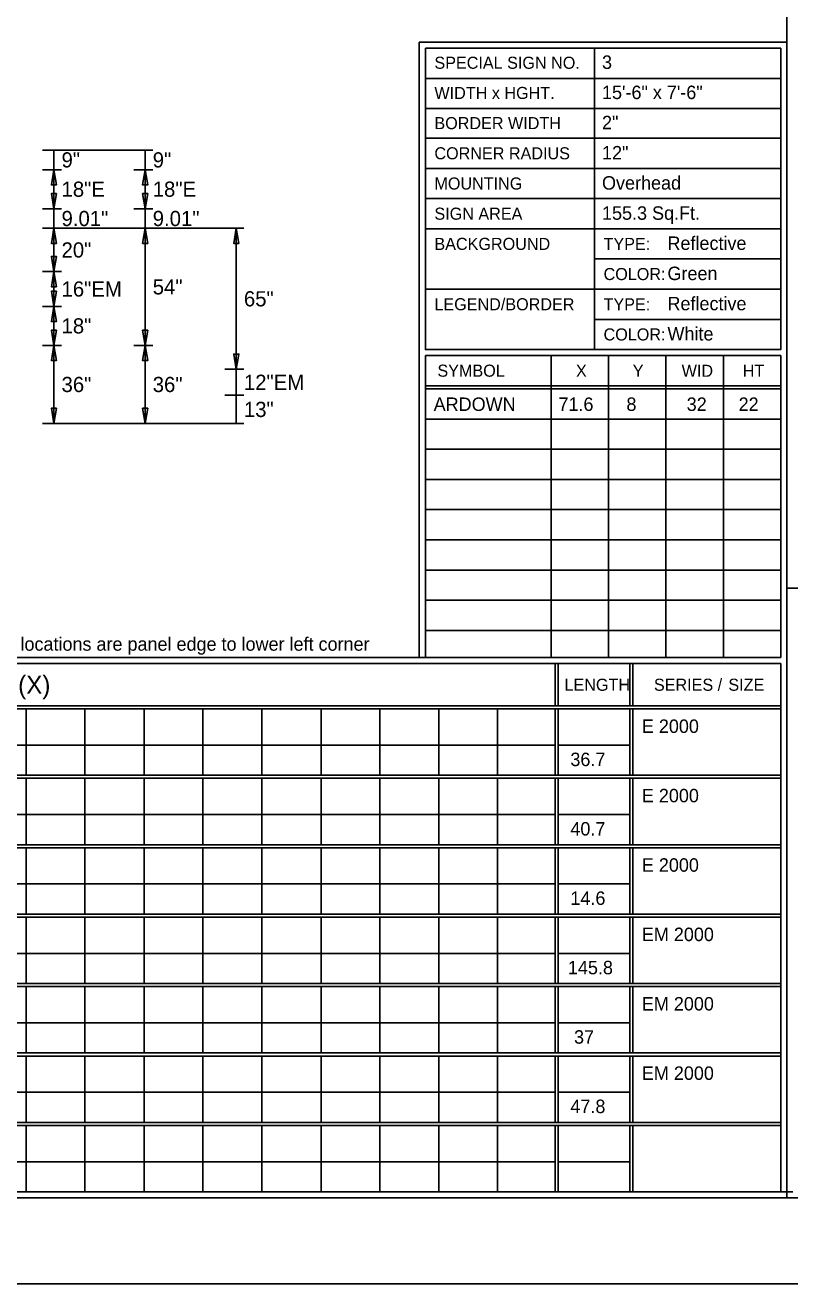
# Model space of a CAD drawing. Extents: x 2149961 to 2150220, y 145114 to 145240.
# Drawn here: x 2150047.08 to 2150076.43, y 145114.09 to 145162.43 of the extents above; entities that cross this region are included whole.
import ezdxf

# ---------------------------------------------------------------- set-up
doc = ezdxf.new("R2010")
doc.units = 0
for name, color, linetype in [('BORDER', 7, 'Continuous'), ('GSDIMS', 7, 'Continuous'), ('GSSHT', 7, 'Continuous'), ('Level 1', 7, 'Continuous'), ('PDF', 7, 'Continuous')]:
    doc.layers.add(name, color=color, linetype=linetype)

msp = doc.modelspace()

# ---------------------------------------------------------------- linework, layer by layer
at = {"layer": 'BORDER'}
for p, q in [((2150017.557, 145117.388), (2150171.536, 145117.388)), ((2150010.458, 145114.088), (2150174.061, 145114.088))]:
    msp.add_line(p, q, dxfattribs=at)
at = {"layer": 'GSDIMS'}
for p, q in [((2150047.749, 145157.634), (2150048.478, 145157.634)), ((2150047.749, 145157.634), (2150051.249, 145157.634)), ((2150048.187, 145156.883), (2150048.187, 145157.634)), ((2150051.249, 145157.634), (2150051.978, 145157.634)), ((2150051.687, 145156.883), (2150051.687, 145157.634)), ((2150047.749, 145156.883), (2150048.478, 145156.883)), ((2150047.749, 145156.883), (2150048.478, 145156.883)), ((2150048.187, 145156.883), (2150048.187, 145155.383)), ((2150051.249, 145156.883), (2150051.978, 145156.883)), ((2150051.249, 145156.883), (2150051.978, 145156.883)), ((2150051.687, 145156.883), (2150051.687, 145155.383)), ((2150047.749, 145155.383), (2150048.478, 145155.383)), ((2150047.749, 145155.383), (2150048.478, 145155.383)), ((2150048.187, 145154.633), (2150048.187, 145155.383)), ((2150051.249, 145155.383), (2150051.978, 145155.383)), ((2150051.249, 145155.383), (2150051.978, 145155.383)), ((2150051.687, 145154.633), (2150051.687, 145155.383)), ((2150047.749, 145154.633), (2150048.478, 145154.633)), ((2150047.749, 145154.633), (2150054.749, 145154.633)), ((2150047.749, 145154.633), (2150048.478, 145154.633)), ((2150047.749, 145154.633), (2150051.249, 145154.633)), ((2150048.187, 145152.966), (2150048.187, 145154.633)), ((2150051.249, 145154.633), (2150051.978, 145154.633)), ((2150051.249, 145154.633), (2150051.978, 145154.633)), ((2150051.687, 145150.133), (2150051.687, 145154.633)), ((2150054.749, 145154.633), (2150055.478, 145154.633)), ((2150055.187, 145149.216), (2150055.187, 145154.633)), ((2150047.749, 145152.966), (2150048.478, 145152.966)), ((2150047.749, 145152.966), (2150048.478, 145152.966)), ((2150048.187, 145152.966), (2150048.187, 145151.633)), ((2150047.749, 145151.633), (2150048.478, 145151.633)), ((2150047.749, 145151.633), (2150048.478, 145151.633)), ((2150048.187, 145150.133), (2150048.187, 145151.633)), ((2150047.749, 145150.133), (2150048.478, 145150.133)), ((2150047.749, 145150.133), (2150048.478, 145150.133)), ((2150048.187, 145150.133), (2150048.187, 145147.133)), ((2150051.249, 145150.133), (2150051.978, 145150.133)), ((2150051.249, 145150.133), (2150051.978, 145150.133)), ((2150051.687, 145150.133), (2150051.687, 145147.133)), ((2150054.749, 145149.216), (2150055.478, 145149.216)), ((2150054.749, 145149.216), (2150055.478, 145149.216)), ((2150055.187, 145149.216), (2150055.187, 145148.216)), ((2150054.749, 145148.216), (2150055.478, 145148.216)), ((2150054.749, 145148.216), (2150055.478, 145148.216)), ((2150055.187, 145147.133), (2150055.187, 145148.216)), ((2150047.749, 145147.133), (2150048.478, 145147.133)), ((2150047.749, 145147.133), (2150054.749, 145147.133)), ((2150051.249, 145147.133), (2150051.978, 145147.133)), ((2150054.749, 145147.133), (2150055.478, 145147.133))]:
    msp.add_line(p, q, dxfattribs=at)
for points in [[(2150048.187, 145156.883), (2150048.09, 145156.3), (2150048.284, 145156.3)], [(2150051.687, 145156.883), (2150051.59, 145156.3), (2150051.784, 145156.3)], [(2150048.187, 145155.383), (2150048.09, 145155.967), (2150048.284, 145155.967)], [(2150051.687, 145155.383), (2150051.59, 145155.967), (2150051.784, 145155.967)], [(2150048.187, 145154.633), (2150048.09, 145154.05), (2150048.284, 145154.05)], [(2150051.687, 145154.633), (2150051.59, 145154.05), (2150051.784, 145154.05)], [(2150055.187, 145154.633), (2150055.09, 145154.05), (2150055.284, 145154.05)], [(2150048.187, 145152.966), (2150048.09, 145153.55), (2150048.284, 145153.55)], [(2150048.187, 145152.966), (2150048.09, 145152.383), (2150048.284, 145152.383)], [(2150048.187, 145151.633), (2150048.09, 145152.216), (2150048.284, 145152.216)], [(2150048.187, 145151.633), (2150048.09, 145151.05), (2150048.284, 145151.05)], [(2150048.187, 145150.133), (2150048.09, 145150.717), (2150048.284, 145150.717)], [(2150051.687, 145150.133), (2150051.59, 145150.717), (2150051.784, 145150.717)], [(2150048.187, 145150.133), (2150048.09, 145149.55), (2150048.284, 145149.55)], [(2150051.687, 145150.133), (2150051.59, 145149.55), (2150051.784, 145149.55)], [(2150055.187, 145149.216), (2150055.09, 145149.8), (2150055.284, 145149.8)], [(2150048.187, 145147.133), (2150048.09, 145147.716), (2150048.284, 145147.716)], [(2150051.687, 145147.133), (2150051.59, 145147.716), (2150051.784, 145147.716)]]:
    msp.add_lwpolyline(points, close=True, dxfattribs=at)
at = {"layer": 'Level 1'}
for p, q in [((2150076.316, 145216.512), (2150076.316, 145117.388)), ((2150062.21, 145161.778), (2150076.316, 145161.778)), ((2150068.935, 145161.546), (2150068.935, 145149.975)), ((2150062.442, 145160.387), (2150076.084, 145160.387)), ((2150062.442, 145159.227), (2150076.084, 145159.227)), ((2150062.442, 145158.091), (2150076.084, 145158.091)), ((2150062.442, 145156.932), (2150076.084, 145156.932)), ((2150062.442, 145155.772), (2150076.084, 145155.772)), ((2150062.442, 145154.613), (2150076.084, 145154.613)), ((2150068.935, 145153.453), (2150076.084, 145153.453)), ((2150062.442, 145152.294), (2150076.084, 145152.294)), ((2150068.935, 145151.134), (2150076.084, 145151.134)), ((2150062.442, 145138.143), (2150062.442, 145149.743)), ((2150062.442, 145149.743), (2150076.084, 145149.743)), ((2150067.272, 145149.737), (2150067.272, 145148.578)), ((2150069.475, 145149.737), (2150069.475, 145148.578)), ((2150071.678, 145149.737), (2150071.678, 145148.578)), ((2150073.881, 145149.737), (2150073.881, 145148.578)), ((2150076.084, 145149.743), (2150076.084, 145138.143)), ((2150062.442, 145148.578), (2150076.084, 145148.578)), ((2150062.442, 145148.462), (2150076.084, 145148.462)), ((2150067.272, 145148.578), (2150067.272, 145138.143)), ((2150069.475, 145148.578), (2150069.475, 145138.143)), ((2150071.678, 145148.578), (2150071.678, 145138.143)), ((2150073.881, 145148.578), (2150073.881, 145138.143)), ((2150062.442, 145147.303), (2150076.084, 145147.303)), ((2150062.442, 145146.143), (2150076.084, 145146.143)), ((2150062.442, 145144.984), (2150076.084, 145144.984)), ((2150062.442, 145143.824), (2150076.084, 145143.824)), ((2150062.442, 145142.665), (2150076.084, 145142.665)), ((2150062.442, 145141.505), (2150076.084, 145141.505)), ((2150076.316, 145140.809), (2150121.342, 145140.809)), ((2150062.442, 145140.346), (2150076.084, 145140.346)), ((2150062.442, 145139.186), (2150076.084, 145139.186)), ((2150017.557, 145138.143), (2150062.583, 145138.143)), ((2150076.084, 145138.143), (2150062.442, 145138.143)), ((2150067.426, 145137.911), (2150067.426, 145136.288)), ((2150067.542, 145137.911), (2150067.542, 145136.288)), ((2150070.29, 145137.911), (2150070.29, 145136.288)), ((2150070.405, 145137.911), (2150070.405, 145136.288)), ((2150017.789, 145136.288), (2150076.084, 145136.288)), ((2150017.789, 145136.172), (2150076.084, 145136.172)), ((2150047.124, 145136.172), (2150047.124, 145133.621)), ((2150049.373, 145136.172), (2150049.373, 145133.621)), ((2150051.646, 145136.172), (2150051.646, 145133.621)), ((2150053.895, 145136.172), (2150053.895, 145133.621)), ((2150056.168, 145136.172), (2150056.168, 145133.621)), ((2150058.441, 145136.172), (2150058.441, 145133.621)), ((2150060.69, 145136.172), (2150060.69, 145133.621)), ((2150062.962, 145136.172), (2150062.962, 145133.621)), ((2150065.212, 145136.172), (2150065.212, 145133.621)), ((2150067.426, 145136.172), (2150067.426, 145133.621)), ((2150067.542, 145136.172), (2150067.542, 145133.621)), ((2150070.29, 145136.172), (2150070.29, 145133.621)), ((2150070.405, 145136.172), (2150070.405, 145133.621)), ((2150017.789, 145134.78), (2150067.426, 145134.78)), ((2150067.542, 145134.78), (2150070.29, 145134.78)), ((2150017.789, 145133.621), (2150076.084, 145133.621)), ((2150017.789, 145133.505), (2150076.084, 145133.505)), ((2150047.124, 145133.505), (2150047.124, 145130.954)), ((2150049.373, 145133.505), (2150049.373, 145130.954)), ((2150051.646, 145133.505), (2150051.646, 145130.954)), ((2150053.895, 145133.505), (2150053.895, 145130.954)), ((2150056.168, 145133.505), (2150056.168, 145130.954)), ((2150058.441, 145133.505), (2150058.441, 145130.954)), ((2150060.69, 145133.505), (2150060.69, 145130.954)), ((2150062.962, 145133.505), (2150062.962, 145130.954)), ((2150065.212, 145133.505), (2150065.212, 145130.954)), ((2150067.426, 145133.505), (2150067.426, 145130.954)), ((2150067.542, 145133.505), (2150067.542, 145130.954)), ((2150070.29, 145133.505), (2150070.29, 145130.954)), ((2150070.405, 145133.505), (2150070.405, 145130.954)), ((2150017.789, 145132.113), (2150067.426, 145132.113)), ((2150067.542, 145132.113), (2150070.29, 145132.113)), ((2150017.789, 145130.954), (2150076.084, 145130.954)), ((2150017.789, 145130.838), (2150076.084, 145130.838)), ((2150047.124, 145130.838), (2150047.124, 145128.287)), ((2150049.373, 145130.838), (2150049.373, 145128.287)), ((2150051.646, 145130.838), (2150051.646, 145128.287)), ((2150053.895, 145130.838), (2150053.895, 145128.287)), ((2150056.168, 145130.838), (2150056.168, 145128.287)), ((2150058.441, 145130.838), (2150058.441, 145128.287)), ((2150060.69, 145130.838), (2150060.69, 145128.287)), ((2150062.962, 145130.838), (2150062.962, 145128.287)), ((2150065.212, 145130.838), (2150065.212, 145128.287)), ((2150067.426, 145130.838), (2150067.426, 145128.287)), ((2150067.542, 145130.838), (2150067.542, 145128.287)), ((2150070.29, 145130.838), (2150070.29, 145128.287)), ((2150070.405, 145130.838), (2150070.405, 145128.287)), ((2150017.789, 145129.447), (2150067.426, 145129.447)), ((2150067.542, 145129.447), (2150070.29, 145129.447)), ((2150017.789, 145128.287), (2150076.084, 145128.287)), ((2150017.789, 145128.171), (2150076.084, 145128.171)), ((2150047.124, 145128.171), (2150047.124, 145125.62)), ((2150049.373, 145128.171), (2150049.373, 145125.62)), ((2150051.646, 145128.171), (2150051.646, 145125.62)), ((2150053.895, 145128.171), (2150053.895, 145125.62)), ((2150056.168, 145128.171), (2150056.168, 145125.62)), ((2150058.441, 145128.171), (2150058.441, 145125.62)), ((2150060.69, 145128.171), (2150060.69, 145125.62)), ((2150062.962, 145128.171), (2150062.962, 145125.62)), ((2150065.212, 145128.171), (2150065.212, 145125.62)), ((2150067.426, 145128.171), (2150067.426, 145125.62)), ((2150067.542, 145128.171), (2150067.542, 145125.62)), ((2150070.29, 145128.171), (2150070.29, 145125.62)), ((2150070.405, 145128.171), (2150070.405, 145125.62)), ((2150017.789, 145126.78), (2150067.426, 145126.78)), ((2150067.542, 145126.78), (2150070.29, 145126.78)), ((2150017.789, 145125.62), (2150076.084, 145125.62)), ((2150017.789, 145125.504), (2150076.084, 145125.504)), ((2150047.124, 145125.504), (2150047.124, 145122.954)), ((2150049.373, 145125.504), (2150049.373, 145122.954)), ((2150051.646, 145125.504), (2150051.646, 145122.954)), ((2150053.895, 145125.504), (2150053.895, 145122.954)), ((2150056.168, 145125.504), (2150056.168, 145122.954)), ((2150058.441, 145125.504), (2150058.441, 145122.954)), ((2150060.69, 145125.504), (2150060.69, 145122.954)), ((2150062.962, 145125.504), (2150062.962, 145122.954)), ((2150065.212, 145125.504), (2150065.212, 145122.954)), ((2150067.426, 145125.504), (2150067.426, 145122.954)), ((2150067.542, 145125.504), (2150067.542, 145122.954)), ((2150070.29, 145125.504), (2150070.29, 145122.954)), ((2150070.405, 145125.504), (2150070.405, 145122.954)), ((2150017.789, 145124.113), (2150067.426, 145124.113)), ((2150067.542, 145124.113), (2150070.29, 145124.113)), ((2150017.789, 145122.954), (2150076.084, 145122.954)), ((2150017.789, 145122.838), (2150076.084, 145122.838)), ((2150047.124, 145122.838), (2150047.124, 145120.287)), ((2150049.373, 145122.838), (2150049.373, 145120.287)), ((2150051.646, 145122.838), (2150051.646, 145120.287)), ((2150053.895, 145122.838), (2150053.895, 145120.287)), ((2150056.168, 145122.838), (2150056.168, 145120.287)), ((2150058.441, 145122.838), (2150058.441, 145120.287)), ((2150060.69, 145122.838), (2150060.69, 145120.287)), ((2150062.962, 145122.838), (2150062.962, 145120.287)), ((2150065.212, 145122.838), (2150065.212, 145120.287)), ((2150067.426, 145122.838), (2150067.426, 145120.287)), ((2150067.542, 145122.838), (2150067.542, 145120.287)), ((2150070.29, 145122.838), (2150070.29, 145120.287)), ((2150070.405, 145122.838), (2150070.405, 145120.287)), ((2150017.789, 145121.446), (2150067.426, 145121.446)), ((2150067.542, 145121.446), (2150070.29, 145121.446)), ((2150017.789, 145120.287), (2150076.084, 145120.287)), ((2150017.789, 145120.171), (2150076.084, 145120.171)), ((2150047.124, 145120.171), (2150047.124, 145117.62)), ((2150049.373, 145120.171), (2150049.373, 145117.62)), ((2150051.646, 145120.171), (2150051.646, 145117.62)), ((2150053.895, 145120.171), (2150053.895, 145117.62)), ((2150056.168, 145120.171), (2150056.168, 145117.62)), ((2150058.441, 145120.171), (2150058.441, 145117.62)), ((2150060.69, 145120.171), (2150060.69, 145117.62)), ((2150062.962, 145120.171), (2150062.962, 145117.62)), ((2150065.212, 145120.171), (2150065.212, 145117.62)), ((2150067.426, 145120.171), (2150067.426, 145117.62)), ((2150067.542, 145120.171), (2150067.542, 145117.62)), ((2150070.29, 145120.171), (2150070.29, 145117.62)), ((2150070.405, 145120.171), (2150070.405, 145117.62)), ((2150017.789, 145118.779), (2150067.426, 145118.779)), ((2150067.542, 145118.779), (2150070.29, 145118.779)), ((2150076.084, 145117.62), (2150076.548, 145117.62))]:
    msp.add_line(p, q, dxfattribs=at)
msp.add_lwpolyline([(2150062.21, 145138.143), (2150062.21, 145161.778)], dxfattribs=at)
for points in [[(2150062.442, 145161.546), (2150076.084, 145161.546), (2150076.084, 145149.975), (2150062.442, 145149.975)], [(2150017.789, 145137.911), (2150076.084, 145137.911), (2150076.084, 145117.62), (2150017.789, 145117.62)]]:
    msp.add_lwpolyline(points, close=True, dxfattribs=at)
at = {"layer": 'PDF'}
msp.add_lwpolyline([(2150010.458, 145114.088), (2150174.061, 145114.088), (2150174.061, 145219.948), (2150010.458, 145219.948)], close=True, dxfattribs=at)

# ---------------------------------------------------------------- texts
at = {"layer": 'GSDIMS'}
for s, p in [('9"', (2150048.478, 145156.967)), ('9"', (2150051.978, 145156.967)), ('18"E', (2150048.478, 145155.842)), ('18"E', (2150051.978, 145155.842)), ('9.01"', (2150048.478, 145154.716)), ('9.01"', (2150051.978, 145154.716)), ('20"', (2150048.478, 145153.508)), ('16"EM', (2150048.478, 145152.008)), ('54"', (2150051.978, 145152.091)), ('65"', (2150055.478, 145151.633)), ('18"', (2150048.478, 145150.591)), ('36"', (2150048.478, 145148.341)), ('36"', (2150051.978, 145148.341)), ('12"EM', (2150055.478, 145148.425)), ('13"', (2150055.478, 145147.383))]:
    msp.add_text(s, height=0.5833, dxfattribs=at).set_placement(p)
at = {"layer": 'GSSHT'}
for s, height, p in [('3', 0.517, (2150069.224, 145160.753)), ('Overhead', 0.5165, (2150069.224, 145156.117))]:
    msp.add_text(s, height=height, dxfattribs=at).set_placement(p)
at = {"layer": 'Level 1'}
for s, height, p in [('SPECIAL SIGN NO.', 0.46374, (2150062.79, 145160.758)), ('WIDTH x HGHT.', 0.46374, (2150062.79, 145159.598)), ('15\'-6" x 7\'-6"', 0.51652, (2150069.224, 145159.594)), ('BORDER WIDTH', 0.46374, (2150062.79, 145158.439)), ('2"', 0.5165, (2150069.224, 145158.435)), ('CORNER RADIUS', 0.46374, (2150062.79, 145157.28)), ('12"', 0.5165, (2150069.224, 145157.276)), ('MOUNTING', 0.4637, (2150062.79, 145156.12)), ('155.3 Sq.Ft.', 0.51652, (2150069.224, 145154.958)), ('SIGN AREA', 0.4638, (2150062.79, 145154.961)), ('BACKGROUND', 0.4637, (2150062.79, 145153.801)), ('TYPE:', 0.4637, (2150069.283, 145153.801)), ('Reflective', 0.5165, (2150071.736, 145153.8)), ('COLOR:', 0.4637, (2150069.283, 145152.642)), ('Green', 0.5165, (2150071.736, 145152.641)), ('LEGEND/BORDER', 0.46374, (2150062.79, 145151.482)), ('TYPE:', 0.4637, (2150069.283, 145151.482)), ('Reflective', 0.5165, (2150071.736, 145151.482)), ('COLOR:', 0.4637, (2150069.283, 145150.323)), ('White', 0.5165, (2150071.736, 145150.323)), ('SYMBOL', 0.4637, (2150062.906, 145148.931)), ('X', 0.464, (2150068.223, 145148.926)), ('Y', 0.464, (2150070.403, 145148.926)), ('WID', 0.4637, (2150072.281, 145148.926)), ('HT', 0.4637, (2150074.623, 145148.926)), ('ARDOWN', 0.5165, (2150062.761, 145147.616)), ('71.6', 0.5165, (2150067.551, 145147.616)), ('8', 0.517, (2150070.16, 145147.616)), ('32', 0.5165, (2150072.474, 145147.616)), ('22', 0.5165, (2150074.467, 145147.616)), ('Letter locations are panel edge to lower left corner', 0.51652, (2150044.943, 145138.406)), ('LETTER POSITIONS (X)', 0.69555, (2150037.664, 145136.751)), ('LENGTH', 0.4638, (2150067.783, 145136.867)), ('LENGTH', 0.4638, (2150067.783, 145136.867)), ('SERIES /', 0.4638, (2150071.216, 145136.867)), ('SIZE', 0.4638, (2150074.074, 145136.867)), ('E 2000', 0.5165, (2150070.753, 145135.248)), ('36.7', 0.5165, (2150068.009, 145133.973)), ('E 2000', 0.5165, (2150070.753, 145132.583)), ('40.7', 0.5165, (2150068.009, 145131.308)), ('E 2000', 0.5165, (2150070.753, 145129.917)), ('14.6', 0.5165, (2150068.009, 145128.643)), ('EM 2000', 0.5165, (2150070.753, 145127.252)), ('145.8', 0.5165, (2150067.915, 145125.977)), ('EM 2000', 0.5165, (2150070.753, 145124.586)), ('37', 0.5165, (2150068.15, 145123.312)), ('EM 2000', 0.5165, (2150070.753, 145121.921)), ('47.8', 0.5165, (2150068.009, 145120.646))]:
    msp.add_text(s, height=height, dxfattribs=at).set_placement(p)

doc.saveas('drawing.dxf')
